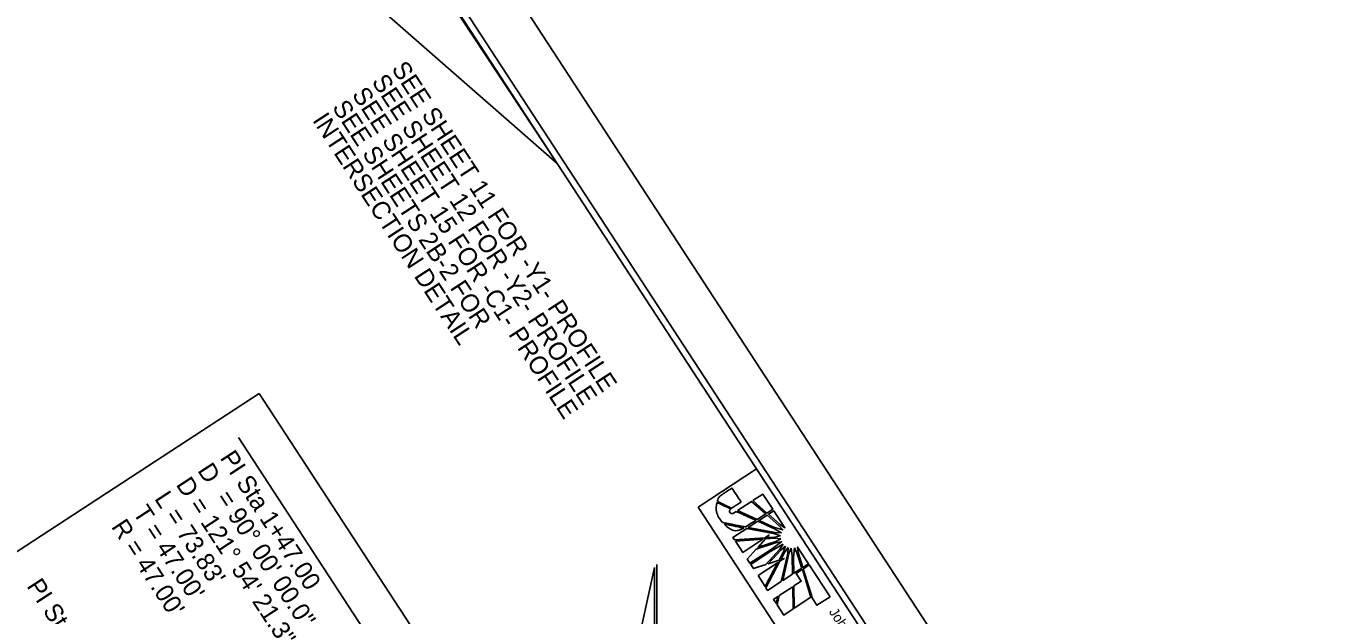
# Model space of a CAD drawing. Extents: x 1639622 to 2864602, y 842655 to 973236.
# Drawn here: x 1640955 to 1641459, y 843492 to 843721 of the extents above; entities that cross this region are included whole.
import ezdxf

# ---------------------------------------------------------------- set-up
doc = ezdxf.new("R2010")
doc.units = 0
for name, color, linetype in [('Prop Dimension', 7, 'Continuous'), ('Prop Dimension Text', 7, 'Continuous'), ('Prop Horizontal Alignment Curve and Spiral Data', 7, 'Continuous'), ('Sheet Clip Boundary CELL', 7, 'Continuous'), ('Sheet North Arrow CELL', 7, 'Continuous'), ('Sheet Plan CELL', 7, 'Continuous'), ('Sheet Plot Border Inside CELL', 7, 'Continuous'), ('Sheet Plot Border Outside CELL', 7, 'Continuous')]:
    doc.layers.add(name, color=color, linetype=linetype)

msp = doc.modelspace()

# ---------------------------------------------------------------- linework, layer by layer
at = {"layer": 'Prop Dimension Text'}
for p, q in [((1641237.49, 843535.72), (1641232.01, 843532.14)), ((1641242.98, 843530.92), (1641237.49, 843535.72)), ((1641241.83, 843538.56), (1641237.94, 843536.01)), ((1641237.94, 843536.01), (1641243.41, 843531.2)), ((1641245.68, 843532.68), (1641241.83, 843538.56)), ((1641232.01, 843532.14), (1641239.58, 843528.69)), ((1641239.58, 843528.69), (1641242.98, 843530.92)), ((1641243.55, 843530.42), (1641240.37, 843528.34)), ((1641243.41, 843531.2), (1641245.68, 843532.68)), ((1641248.12, 843526.38), (1641243.55, 843530.42)), ((1641246.11, 843532.09), (1641244, 843530.71)), ((1641244, 843530.71), (1641248.58, 843526.68)), ((1641250.43, 843525.48), (1641246.11, 843532.09)), ((1641235.57, 843525.2), (1641230.23, 843521.71)), ((1641246.53, 843523.16), (1641235.57, 843525.2)), ((1641239.85, 843528), (1641236.19, 843525.6)), ((1641236.19, 843525.6), (1641246.69, 843523.62)), ((1641246.42, 843525.03), (1641239.85, 843528)), ((1641240.37, 843528.34), (1641246.04, 843525.75)), ((1641246.04, 843525.75), (1641249.61, 843524.61)), ((1641249.02, 843523.53), (1641246.42, 843525.03)), ((1641249.61, 843524.61), (1641248.12, 843526.38)), ((1641248.58, 843526.68), (1641250.43, 843525.48)), ((1641230.23, 843521.71), (1641230.87, 843520.74)), ((1641230.87, 843520.74), (1641242.68, 843521.62)), ((1641241.84, 843521.06), (1641231.16, 843520.29)), ((1641231.16, 843520.29), (1641234.03, 843515.9)), ((1641234.03, 843515.9), (1641241.84, 843521.06)), ((1641242.91, 843521.12), (1641240, 843517.87)), ((1641240, 843517.87), (1641246.86, 843520.18)), ((1641242.68, 843521.62), (1641244.24, 843522.63)), ((1641246.53, 843521.39), (1641242.91, 843521.12)), ((1641244.24, 843522.63), (1641243.36, 843521.64)), ((1641243.36, 843521.64), (1641246.4, 843521.88)), ((1641244.68, 843516.78), (1641249.15, 843520.06)), ((1641246.4, 843521.88), (1641248.75, 843522.39)), ((1641248.75, 843522.39), (1641246.53, 843523.16)), ((1641248.78, 843521.2), (1641246.53, 843521.39)), ((1641246.69, 843523.62), (1641249.02, 843523.53)), ((1641249.15, 843520.06), (1641246.75, 843519.64)), ((1641246.86, 843520.18), (1641248.78, 843521.2)), ((1641239.31, 843517.14), (1641235.8, 843513.26)), ((1641236.85, 843511.65), (1641244.68, 843516.78)), ((1641244.96, 843516.36), (1641237.12, 843511.24)), ((1641246.75, 843519.64), (1641239.31, 843517.14)), ((1641243.07, 843511.18), (1641248.41, 843517.09)), ((1641248.91, 843516.9), (1641243.97, 843511.5)), ((1641249.79, 843519.09), (1641244.96, 843516.36)), ((1641248.16, 843512.89), (1641249.91, 843516.21)), ((1641248.41, 843517.09), (1641249.79, 843519.09)), ((1641250.32, 843515.88), (1641248.81, 843513.09)), ((1641250.67, 843518.32), (1641248.91, 843516.9)), ((1641248.96, 843504.58), (1641251.55, 843515.48)), ((1641252.01, 843515.41), (1641249.57, 843504.98)), ((1641249.91, 843516.21), (1641250.67, 843518.32)), ((1641251.73, 843517.83), (1641250.32, 843515.88)), ((1641251.55, 843515.48), (1641251.73, 843517.83)), ((1641252.89, 843517.6), (1641252.01, 843515.41)), ((1641253.24, 843514.59), (1641252.89, 843517.6)), ((1641254.14, 843517.69), (1641253.73, 843513.91)), ((1641255.09, 843515.72), (1641254.14, 843517.69)), ((1641257, 843509.78), (1641255.09, 843515.72)), ((1641259.56, 843511.46), (1641255.33, 843517.99)), ((1641255.33, 843517.99), (1641255.63, 843515.84)), ((1641255.63, 843515.84), (1641257.44, 843510.07)), ((1641235.8, 843513.26), (1641236.85, 843511.65)), ((1641237.12, 843511.24), (1641238.19, 843509.61)), ((1641238.19, 843509.61), (1641243.07, 843511.18)), ((1641247.61, 843511.88), (1641239.97, 843506.88)), ((1641242.72, 843502.68), (1641247.61, 843511.88)), ((1641248.45, 843512.43), (1641243.01, 843502.17)), ((1641243.97, 843511.5), (1641248.16, 843512.89)), ((1641250.17, 843513.55), (1641248.45, 843512.43)), ((1641248.81, 843513.09), (1641250.17, 843513.55)), ((1641253.34, 843507.44), (1641253.24, 843514.59)), ((1641253.73, 843513.91), (1641253.86, 843507.79)), ((1641253.86, 843507.79), (1641257, 843509.78)), ((1641257.44, 843510.07), (1641259.56, 843511.46)), ((1641259.88, 843511.02), (1641257.61, 843509.54)), ((1641267.96, 843498.67), (1641259.88, 843511.02)), ((1641239.97, 843506.88), (1641242.72, 843502.68)), ((1641249.57, 843504.98), (1641253.34, 843507.44)), ((1641257.16, 843509.24), (1641254.79, 843507.69)), ((1641254.79, 843507.69), (1641256.77, 843504.67)), ((1641257.2, 843509.26), (1641257.16, 843509.24)), ((1641260.55, 843498.46), (1641257.2, 843509.26)), ((1641257.61, 843509.54), (1641257.55, 843509.49)), ((1641257.55, 843509.49), (1641261.18, 843497.98)), ((1641243.01, 843502.17), (1641243.69, 843501.13)), ((1641243.69, 843501.13), (1641248.96, 843504.58)), ((1641253.46, 843502.51), (1641248.2, 843499.08)), ((1641253.61, 843493.92), (1641253.46, 843502.51)), ((1641256.77, 843504.67), (1641253.94, 843502.83)), ((1641253.94, 843502.83), (1641254.07, 843494.22)), ((1641247.63, 843498.7), (1641245.98, 843497.62)), ((1641245.98, 843497.62), (1641246.98, 843496.1)), ((1641246.98, 843496.1), (1641247.63, 843498.7)), ((1641248.2, 843499.08), (1641247.36, 843495.52)), ((1641247.36, 843495.52), (1641249.96, 843491.53)), ((1641254.07, 843494.22), (1641260.55, 843498.46)), ((1641261.18, 843497.98), (1641262.9, 843495.36)), ((1641262.9, 843495.36), (1641267.96, 843498.67)), ((1641249.96, 843491.53), (1641253.61, 843493.92))]:
    msp.add_line(p, q, dxfattribs=at)
msp.add_lwpolyline([(1641216.75, 843533.53), (1641298.74, 843407.89), (1641321.42, 843422.68), (1641239.43, 843548.33)], close=True, dxfattribs=at)
for points in [[(1641232.01, 843532.14), (1641239.58, 843528.69), (1641242.98, 843530.92), (1641237.49, 843535.72), (1641232.01, 843532.14)], [(1641237.94, 843536.01), (1641243.41, 843531.2), (1641245.68, 843532.68), (1641241.83, 843538.56), (1641237.94, 843536.01)], [(1641243.55, 843530.42), (1641240.37, 843528.34), (1641246.04, 843525.75), (1641249.61, 843524.61), (1641248.12, 843526.38), (1641243.55, 843530.42)], [(1641248.58, 843526.68), (1641250.43, 843525.48), (1641246.11, 843532.09), (1641244, 843530.71), (1641248.58, 843526.68)], [(1641248.75, 843522.39), (1641246.53, 843523.16), (1641235.57, 843525.2), (1641230.23, 843521.71), (1641230.87, 843520.74), (1641242.68, 843521.62), (1641244.24, 843522.63), (1641243.36, 843521.64), (1641246.4, 843521.88), (1641248.75, 843522.39)], [(1641239.85, 843528), (1641236.19, 843525.6), (1641246.69, 843523.62), (1641249.02, 843523.53), (1641246.42, 843525.03), (1641239.85, 843528)], [(1641231.16, 843520.29), (1641234.03, 843515.9), (1641241.84, 843521.06), (1641231.16, 843520.29)], [(1641246.75, 843519.64), (1641239.31, 843517.14), (1641235.8, 843513.26), (1641236.85, 843511.65), (1641244.68, 843516.78), (1641249.15, 843520.06), (1641246.75, 843519.64)], [(1641248.78, 843521.2), (1641246.53, 843521.39), (1641242.91, 843521.12), (1641240, 843517.87), (1641246.86, 843520.18), (1641248.78, 843521.2)], [(1641249.79, 843519.09), (1641244.96, 843516.36), (1641237.12, 843511.24), (1641238.19, 843509.61), (1641243.07, 843511.18), (1641248.41, 843517.09), (1641249.79, 843519.09)], [(1641251.73, 843517.83), (1641250.32, 843515.88), (1641248.81, 843513.09), (1641250.17, 843513.55), (1641248.45, 843512.43), (1641243.01, 843502.17), (1641243.69, 843501.13), (1641248.96, 843504.58), (1641251.55, 843515.48), (1641251.73, 843517.83)], [(1641250.67, 843518.32), (1641248.91, 843516.9), (1641243.97, 843511.5), (1641248.16, 843512.89), (1641249.91, 843516.21), (1641250.67, 843518.32)], [(1641252.89, 843517.6), (1641252.01, 843515.41), (1641249.57, 843504.98), (1641253.34, 843507.44), (1641253.24, 843514.59), (1641252.89, 843517.6)], [(1641254.14, 843517.69), (1641253.73, 843513.91), (1641253.86, 843507.79), (1641257, 843509.78), (1641255.09, 843515.72), (1641254.14, 843517.69)], [(1641255.63, 843515.84), (1641257.44, 843510.07), (1641259.56, 843511.46), (1641255.33, 843517.99), (1641255.63, 843515.84)], [(1641239.97, 843506.88), (1641242.72, 843502.68), (1641247.61, 843511.88), (1641239.97, 843506.88)], [(1641267.96, 843498.67), (1641259.88, 843511.02), (1641257.61, 843509.54), (1641257.55, 843509.49), (1641261.18, 843497.98), (1641262.9, 843495.36), (1641267.96, 843498.67)], [(1641257.2, 843509.26), (1641257.16, 843509.24), (1641254.79, 843507.69), (1641256.77, 843504.67), (1641253.94, 843502.83), (1641254.07, 843494.22), (1641260.55, 843498.46), (1641257.2, 843509.26)], [(1641253.46, 843502.51), (1641248.2, 843499.08), (1641247.36, 843495.52), (1641249.96, 843491.53), (1641253.61, 843493.92), (1641253.46, 843502.51), (1641253.46, 843502.51)], [(1641245.98, 843497.62), (1641245.98, 843497.62), (1641246.98, 843496.1), (1641247.63, 843498.7), (1641245.98, 843497.62)]]:
    msp.add_lwpolyline(points, dxfattribs=at)
for points in [[(1641233.43, 843535.47), (1641233.43, 843535.47), (1641229.87, 843540.91), (1641229.87, 843540.91), (1641229.87, 843540.91), (1641226.47, 843538.69), (1641226.47, 843538.69), (1641226.47, 843538.69), (1641226.11, 843538.45), (1641226.11, 843538.45), (1641225.04, 843537.75), (1641224.43, 843536.85), (1641224.13, 843535.77), (1641224.13, 843535.77), (1641229.76, 843533.07), (1641229.83, 843533.12), (1641229.83, 843533.12), (1641233.43, 843535.47), (1641233.43, 843535.47)], [(1641229.08, 843531.43), (1641228.86, 843531.77), (1641228.85, 843532.2), (1641229.42, 843532.75), (1641229.42, 843532.75), (1641224.05, 843535.27), (1641224.05, 843535.27), (1641223.54, 843533.07), (1641224.08, 843530.46), (1641225.23, 843528.71), (1641225.53, 843528.25), (1641225.79, 843527.93), (1641226.21, 843527.51), (1641226.21, 843527.51), (1641235.14, 843525.79), (1641235.14, 843525.79), (1641235.14, 843525.79), (1641239.09, 843528.38), (1641239.09, 843528.38), (1641239.09, 843528.38), (1641231.52, 843531.81), (1641231.52, 843531.81), (1641230.03, 843530.84), (1641229.4, 843530.94), (1641229.08, 843531.43)], [(1641229.08, 843531.43), (1641228.86, 843531.77), (1641228.85, 843532.2), (1641229.42, 843532.75), (1641229.42, 843532.75), (1641224.05, 843535.27), (1641224.05, 843535.27), (1641223.54, 843533.07), (1641224.08, 843530.46), (1641225.23, 843528.71), (1641225.53, 843528.25), (1641225.79, 843527.93), (1641226.21, 843527.51), (1641226.21, 843527.51), (1641235.14, 843525.79), (1641235.14, 843525.79), (1641235.14, 843525.79), (1641239.09, 843528.38), (1641239.09, 843528.38), (1641239.09, 843528.38), (1641231.52, 843531.81), (1641231.52, 843531.81), (1641230.03, 843530.84), (1641229.4, 843530.94), (1641229.08, 843531.43)], [(1641234.52, 843525.38), (1641234.52, 843525.38), (1641226.8, 843526.87), (1641226.8, 843526.87), (1641228.82, 843524.99), (1641231.76, 843523.73), (1641234.52, 843525.38)]]:
    msp.add_open_spline(points, degree=3, dxfattribs=at)
at = {"layer": 'Prop Horizontal Alignment Curve and Spiral Data'}
msp.add_line((1641038.07, 843560.52), (1641155.09, 843381.18), dxfattribs=at)
msp.add_lwpolyline([(1641046, 843577.64), (1641173.64, 843382.04), (1641010.85, 843275.81), (1640883.22, 843471.41)], close=True, dxfattribs=at)
at = {"layer": 'Sheet Clip Boundary CELL'}
msp.add_lwpolyline([(1640897.11, 844068.08), (1641161.94, 843667.07), (1640998.54, 843810.18), (1640864.06, 843725.83)], dxfattribs=at)
at = {"layer": 'Sheet North Arrow CELL'}
msp.add_line((1641200.65, 843381.18), (1641200.65, 843511.18), dxfattribs=at)
msp.add_lwpolyline([(1641199.75, 843510.04), (1641192.33, 843476.28), (1641199.75, 843480.04)], close=True, dxfattribs=at)
at = {"layer": 'Sheet Plan CELL'}
for points in [[(1641430.74, 843255.12), (1640611, 844511.36), (1639731.66, 843937.55), (1640551.38, 842681.33)], [(1639731.66, 843937.55), (1640610.97, 844511.36), (1641321.42, 843422.68), (1641195.75, 843340.66), (1641305.06, 843173.13), (1640551.38, 842681.33)]]:
    msp.add_lwpolyline(points, close=True, dxfattribs=at)
at = {"layer": 'Sheet Plot Border Inside CELL'}
msp.add_lwpolyline([(1639645.67, 844064.72), (1640556.11, 842669.51), (1641439.64, 843246.03), (1640529.21, 844641.26)], close=True, dxfattribs=at)
at = {"layer": 'Sheet Plot Border Outside CELL'}
msp.add_lwpolyline([(1639621.82, 844064.68), (1640541.82, 842654.79), (1641458.85, 843253.19), (1640538.85, 844663.07)], close=True, dxfattribs=at)
msp.add_lwpolyline([(1639621.82, 844064.68), (1640541.82, 842654.79), (1641458.85, 843253.19), (1640538.85, 844663.07)], close=True, dxfattribs=at)

# ---------------------------------------------------------------- texts
at = {"layer": 'Prop Dimension'}
for s, p in [('SEE SHEET 11 FOR -Y1- PROFILE', (1641097.29, 843703.97)), ('SEE SHEET 12 FOR -Y2- PROFILE', (1641089.6, 843698.96)), ('SEE SHEET 15 FOR -C1- PROFILE', (1641081.92, 843693.94)), ('SEE SHEETS 2B-2 FOR', (1641074.23, 843688.93)), ('INTERSECTION DETAIL', (1641066.55, 843683.92))]:
    msp.add_text(s, height=7, rotation=303.1259, dxfattribs=at).set_placement(p)
at = {"layer": 'Prop Dimension Text'}
msp.add_text('Johnson, Mirmiran, & Thompson Inc.', height=3.8334, rotation=303.1259, dxfattribs=at).set_placement((1641267.39, 843492.79))
at = {"layer": 'Prop Horizontal Alignment Curve and Spiral Data'}
for s, p in [('PI Sta 1+47.00', (1641030.62, 843552.64)), ('D', (1641021.87, 843547.74)), ('D = 121%%d 54\' 21.3"', (1641013.5, 843542.28)), ("L = 73.83'", (1641005.12, 843536.81)), ("T = 47.00'", (1640996.75, 843531.35)), ('= 90%%d 00\' 00.0" (LT)', (1641029.14, 843537.14)), ("R = 47.00'", (1640988.37, 843525.88)), ('PI Sta 2+94.65', (1640955.49, 843502.82)), ('D = 121%%d 54\' 21.3"', (1640938.37, 843492.45))]:
    msp.add_text(s, height=7, rotation=303.1259, dxfattribs=at).set_placement(p)

doc.saveas('drawing.dxf')
